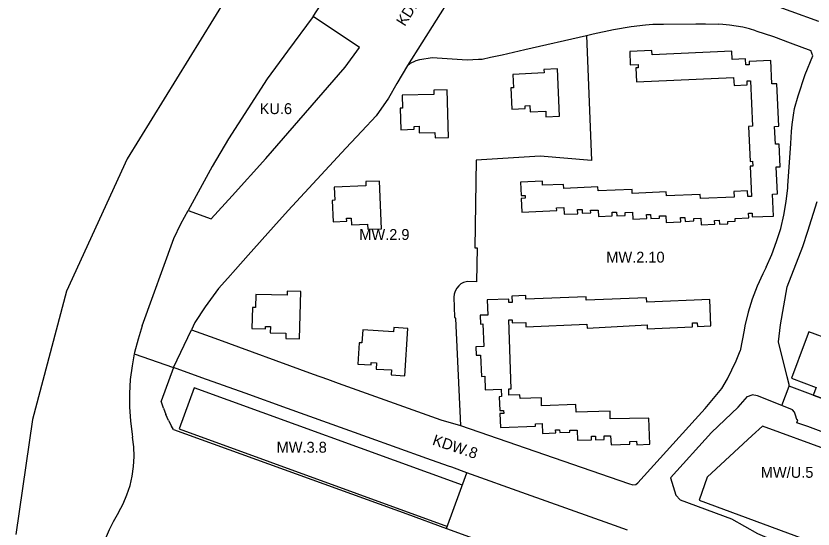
# Model space of a CAD drawing. Extents: x 7428239 to 7429836, y 5549133 to 5550853.
# Drawn here: x 7428328.4 to 7428694.2, y 5550030.9 to 5550266.4 of the extents above; entities that cross this region are included whole.
import ezdxf

# ---------------------------------------------------------------- set-up
doc = ezdxf.new("R2010")
doc.units = 0
for name, color, linetype in [('LIN_linie rozgraniczające', 7, 'Continuous'), ('LIN_nieprzekraczalna linia zabudowy', 7, 'Continuous'), ('LIN_obowiązująca linia zabudowy', 7, 'Continuous'), ('TXT_Oznaczenia Przeznaczenia', 7, 'Continuous')]:
    doc.layers.add(name, color=color, linetype=linetype)

msp = doc.modelspace()

# ---------------------------------------------------------------- linework, layer by layer
at = {"layer": 'LIN_linie rozgraniczające'}
for p, q in [((7428464.78, 5550266.18), (7428486.59, 5550299.96)), ((7428528.83, 5550276.64), (7428508.09, 5550243.65)), ((7428486.06, 5550251.96), (7428464.78, 5550266.18)), ((7428479.54, 5550242.96), (7428486.06, 5550251.96)), ((7428694.09, 5550248.12), (7428693.18, 5550250.53)), ((7428443.14, 5550200.99), (7428479.54, 5550242.96)), ((7428499.35, 5550228.63), (7428493.77, 5550220.64)), ((7428493.77, 5550220.64), (7428487.09, 5550213.47)), ((7428487.09, 5550213.47), (7428479.83, 5550205.67)), ((7428479.83, 5550205.67), (7428453.32, 5550177.17)), ((7428427.7, 5550183.88), (7428443.14, 5550200.99)), ((7428417.98, 5550173.31), (7428427.7, 5550183.88)), ((7428404.11, 5550171.01), (7428407.41, 5550177.08)), ((7428407.41, 5550177.08), (7428417.98, 5550173.31)), ((7428453.32, 5550177.17), (7428446.54, 5550169.55)), ((7428400.9, 5550164.25), (7428404.11, 5550171.01)), ((7428435.04, 5550156.63), (7428446.54, 5550169.55)), ((7428386.41, 5550124.13), (7428400.9, 5550164.25)), ((7428538.94, 5550159.95), (7428539.99, 5550159.97)), ((7428539.99, 5550159.97), (7428539.8, 5550144.41)), ((7428435.04, 5550156.63), (7428429.23, 5550150.1)), ((7428429.23, 5550150.1), (7428425.63, 5550146.08)), ((7428425.63, 5550146.08), (7428421.38, 5550141.34)), ((7428535.56, 5550144.51), (7428533.74, 5550144.09)), ((7428421.38, 5550141.34), (7428415.2, 5550132.9)), ((7428530.7, 5550141.4), (7428530, 5550140.05)), ((7428531.58, 5550142.56), (7428530.7, 5550141.4)), ((7428532.55, 5550143.4), (7428531.58, 5550142.56)), ((7428533.74, 5550144.09), (7428532.55, 5550143.4)), ((7428679.2, 5550124.67), (7428682.3, 5550142.05)), ((7428529.55, 5550138.74), (7428529.37, 5550137.28)), ((7428529.37, 5550137.28), (7428529.71, 5550128.19)), ((7428530, 5550140.05), (7428529.55, 5550138.74)), ((7428415.2, 5550132.9), (7428410.56, 5550125.65)), ((7428529.71, 5550128.19), (7428530.19, 5550127.56)), ((7428530.19, 5550127.56), (7428532.45, 5550078.39)), ((7428410.56, 5550125.65), (7428408.98, 5550122.32)), ((7428678.37, 5550116.76), (7428679.2, 5550124.67)), ((7428400.7, 5550104.99), (7428408.98, 5550122.32)), ((7428408.98, 5550122.32), (7428419.68, 5550118.44)), ((7428662.55, 5550122.24), (7428660.79, 5550112.72)), ((7428419.68, 5550118.44), (7428464.85, 5550102.05)), ((7428658.93, 5550108.11), (7428660.79, 5550112.72)), ((7428382.75, 5550111.37), (7428400.7, 5550104.99)), ((7428654.98, 5550099.8), (7428658.93, 5550108.11)), ((7428400.7, 5550104.99), (7428395.13, 5550089.64)), ((7428413.75, 5550100.32), (7428400.7, 5550104.99)), ((7428464.85, 5550102.05), (7428471.44, 5550099.69)), ((7428433.61, 5550093.21), (7428413.75, 5550100.32)), ((7428471.44, 5550099.69), (7428476.34, 5550097.92)), ((7428476.34, 5550097.92), (7428523.39, 5550081.02)), ((7428652.29, 5550095.38), (7428654.98, 5550099.8)), ((7428644.74, 5550086.16), (7428652.29, 5550095.38)), ((7428679.8, 5550087.58), (7428683.29, 5550096.41)), ((7428396.14, 5550086.34), (7428395.13, 5550089.64)), ((7428452.98, 5550086.26), (7428433.61, 5550093.21)), ((7428396.14, 5550086.34), (7428397.2, 5550083.53)), ((7428489.73, 5550073.1), (7428452.98, 5550086.26)), ((7428640.07, 5550081.15), (7428644.74, 5550086.16)), ((7428398.43, 5550080.79), (7428397.2, 5550083.53)), ((7428336.04, 5550081.17), (7428328.43, 5550028.45)), ((7428398.43, 5550080.79), (7428399.83, 5550078.14)), ((7428613.76, 5550052.06), (7428640.07, 5550081.15)), ((7428400.79, 5550076.64), (7428399.83, 5550078.14)), ((7428400.79, 5550076.64), (7428507.72, 5550037.84)), ((7428532.45, 5550078.39), (7428609.58, 5550051.75)), ((7428516.97, 5550063.33), (7428489.73, 5550073.1)), ((7428526.89, 5550059.77), (7428516.97, 5550063.33)), ((7428526.04, 5550031.19), (7428535.32, 5550056.75)), ((7428528.37, 5550059.24), (7428526.89, 5550059.77)), ((7428609.58, 5550051.75), (7428611.47, 5550051.24)), ((7428611.47, 5550051.24), (7428612.89, 5550051.37)), ((7428612.89, 5550051.37), (7428613.76, 5550052.06)), ((7428600.93, 5550033.25), (7428562.63, 5550046.97)), ((7428609.06, 5550030.33), (7428600.93, 5550033.25))]:
    msp.add_line(p, q, dxfattribs=at)
for points in [[(7428540.94, 5550471.5), (7428527.62, 5550433.97), (7428484.97, 5550367.83), (7428424.73, 5550274.49), (7428379.41, 5550200.89), (7428351.69, 5550140.08), (7428336.04, 5550081.17)], [(7428665.17, 5550274.78), (7428671.25, 5550273.2), (7428696.63, 5550264.05)], [(7428464.78, 5550266.18), (7428453.07, 5550250.24), (7428443.69, 5550237.53), (7428425.98, 5550210.05), (7428418.45, 5550197.38), (7428407.41, 5550177.08)], [(7428508.09, 5550243.65), (7428509.11, 5550244.58), (7428512.14, 5550245.99), (7428513.77, 5550246.5), (7428519.4, 5550247.35), (7428535.4, 5550246.28), (7428540.72, 5550246.51), (7428542.29, 5550246.65), (7428546.23, 5550247.48), (7428551.59, 5550248.62), (7428561.96, 5550251.01), (7428590.2, 5550257.4), (7428593.29, 5550258.17), (7428602.64, 5550260.17), (7428610.75, 5550261.58), (7428617.36, 5550262.36), (7428620.6, 5550262.6), (7428623.19, 5550262.6), (7428625.56, 5550262.69), (7428640.47, 5550262.72), (7428644.86, 5550262.74), (7428650.94, 5550262.57)], [(7428667.95, 5550259.6), (7428664.98, 5550260.49), (7428661.97, 5550261.22), (7428658.93, 5550261.8), (7428655.86, 5550262.23), (7428652.77, 5550262.49), (7428650.94, 5550262.57)], [(7428667.95, 5550259.6), (7428676.02, 5550256.95), (7428683.67, 5550254.15), (7428693.18, 5550250.53)], [(7428590.2, 5550257.4), (7428592.52, 5550200.13), (7428569.03, 5550202.12), (7428539.63, 5550200.24), (7428538.94, 5550159.95)], [(7428682.66, 5550188.41), (7428684, 5550207.84), (7428684.37, 5550213.36), (7428684.64, 5550216.59), (7428685.25, 5550220.87), (7428685.75, 5550223.97), (7428687.35, 5550229.69), (7428690.55, 5550239.58), (7428694.09, 5550248.12)], [(7428508.09, 5550243.65), (7428503.27, 5550235.43), (7428499.35, 5550228.63)], [(7428672.64, 5550151.17), (7428675.25, 5550156.93), (7428677.49, 5550162.84), (7428679.35, 5550168.89), (7428680.83, 5550175.04), (7428681.91, 5550181.27), (7428682.6, 5550187.55), (7428682.66, 5550188.41)], [(7428682.3, 5550142.05), (7428689.53, 5550160.66), (7428691.77, 5550167.64), (7428696.15, 5550181.23)], [(7428672.64, 5550151.17), (7428671.13, 5550148.1)], [(7428539.8, 5550144.41), (7428535.56, 5550144.51)], [(7428671.13, 5550148.1), (7428668.52, 5550142.34), (7428666.28, 5550136.43), (7428664.42, 5550130.38), (7428662.94, 5550124.23), (7428662.55, 5550122.24)], [(7428386.41, 5550124.13), (7428384.45, 5550118.11), (7428382.87, 5550111.99), (7428382.75, 5550111.37), (7428381.69, 5550105.78), (7428380.9, 5550099.5), (7428380.51, 5550093.19), (7428380.52, 5550086.87), (7428380.92, 5550080.56), (7428381.73, 5550074.28), (7428381.92, 5550073.12)], [(7428683.29, 5550096.41), (7428683.29, 5550097.21), (7428682.38, 5550100.84), (7428678.37, 5550116.76)], [(7428733.88, 5550078.05), (7428694.3, 5550092.41), (7428683.29, 5550096.41)], [(7428659.8, 5550086.81), (7428664.15, 5550091.74), (7428666.26, 5550092.52)], [(7428679.8, 5550087.58), (7428668.65, 5550091.99), (7428666.26, 5550092.52)], [(7428659.8, 5550086.81), (7428647.66, 5550075.24), (7428628.82, 5550054.34)], [(7428761.01, 5550059.22), (7428759.96, 5550058.64), (7428755.65, 5550058.66), (7428754.95, 5550058.66), (7428754.25, 5550058.97), (7428745.09, 5550062.01), (7428730.44, 5550066.4), (7428729.5, 5550066.01), (7428727.12, 5550065.03), (7428714.51, 5550069.34), (7428691.75, 5550077.92), (7428686.8, 5550079.72), (7428687.28, 5550081.07), (7428686.76, 5550081.22), (7428686.13, 5550083.11), (7428685.63, 5550084.53), (7428684.79, 5550085.6), (7428679.8, 5550087.58)], [(7428523.39, 5550081.02), (7428532.45, 5550078.39)], [(7428375.46, 5550038.45), (7428377.6, 5550042.41), (7428379.38, 5550046.54), (7428380.78, 5550050.82), (7428381.81, 5550055.2), (7428382.43, 5550059.66), (7428382.66, 5550064.15), (7428382.49, 5550068.65), (7428381.93, 5550073.11), (7428381.92, 5550073.12)], [(7428562.63, 5550046.97), (7428535.32, 5550056.75), (7428528.37, 5550059.24)], [(7428628.82, 5550054.34), (7428631.27, 5550046.51), (7428633.22, 5550044.37), (7428656.8, 5550035.59), (7428668.69, 5550028.81), (7428681.6, 5550023.4), (7428694.78, 5550018.71)], [(7428375.46, 5550038.45), (7428373.05, 5550034.2), (7428371.22, 5550030.6), (7428367.8, 5550022.68)], [(7428507.72, 5550037.84), (7428526.04, 5550031.19), (7428629.86, 5549993.52), (7428630.3, 5549993.32)]]:
    msp.add_lwpolyline(points, dxfattribs=at)
at = {"layer": 'LIN_nieprzekraczalna linia zabudowy'}
for points in [[(7428407.41, 5550177.08), (7428417.98, 5550173.31), (7428427.7, 5550183.88), (7428443.14, 5550200.99), (7428479.54, 5550242.96), (7428486.06, 5550251.96), (7428464.78, 5550266.18), (7428453.07, 5550250.24), (7428443.69, 5550237.53), (7428425.98, 5550210.05), (7428418.45, 5550197.38), (7428407.41, 5550177.08)], [(7428730.33, 5550102.14), (7428732.09, 5550106.68), (7428692.23, 5550121.39), (7428690.6, 5550117.05), (7428684.24, 5550100.1), (7428695.57, 5550095.81), (7428694.3, 5550092.41), (7428711.24, 5550086.26), (7428712.45, 5550089.61), (7428724.1, 5550085.39), (7428730.33, 5550102.14)], [(7428533.27, 5550051.11), (7428410.25, 5550095.78), (7428403.36, 5550076.85), (7428526.39, 5550032.14)], [(7428715.06, 5550061.91), (7428701.07, 5550067.07), (7428671.04, 5550078.17), (7428666.19, 5550073.87), (7428645.67, 5550054.64), (7428641.86, 5550044.19), (7428700.72, 5550022.48), (7428715.06, 5550061.91)]]:
    msp.add_lwpolyline(points, dxfattribs=at)
at = {"layer": 'LIN_obowiązująca linia zabudowy'}
for points in [[(7428570, 5550190.55), (7428559.98, 5550190.14), (7428560.23, 5550183.99), (7428562.06, 5550184.06), (7428562.11, 5550182.7), (7428560.32, 5550182.63), (7428560.58, 5550176.4), (7428576.6, 5550177.06), (7428576.53, 5550178.35), (7428579.87, 5550178.48), (7428580, 5550175.39), (7428586.2, 5550175.65), (7428586.13, 5550177.5), (7428588.23, 5550177.58), (7428588.3, 5550175.84), (7428592.18, 5550176), (7428592.13, 5550177.2), (7428595.57, 5550177.34), (7428595.69, 5550174.4), (7428602.07, 5550174.67), (7428602.01, 5550176.31), (7428604.04, 5550176.4), (7428604.1, 5550174.72), (7428607.96, 5550174.88), (7428607.9, 5550176.21), (7428611.29, 5550176.36), (7428611.43, 5550173.17), (7428617.89, 5550173.46), (7428617.81, 5550175.26), (7428619.6, 5550175.34), (7428619.69, 5550173.43), (7428623.76, 5550173.61), (7428623.71, 5550174.6), (7428626.7, 5550174.73), (7428626.84, 5550171.65), (7428633.51, 5550171.94), (7428633.42, 5550173.84), (7428635.42, 5550173.93), (7428635.5, 5550172.13), (7428639.46, 5550172.3), (7428639.41, 5550173.38), (7428642.68, 5550173.52), (7428642.81, 5550170.59), (7428649.05, 5550170.86), (7428648.98, 5550172.57), (7428651.15, 5550172.67), (7428651.23, 5550170.88), (7428655.12, 5550171.05), (7428655.07, 5550172.06), (7428658.45, 5550172.21), (7428658.39, 5550173.44), (7428664.66, 5550173.72), (7428664.56, 5550175.87), (7428666.2, 5550175.94), (7428666.28, 5550174.15), (7428675.99, 5550174.58), (7428675.55, 5550184.67), (7428677.86, 5550184.77), (7428677.32, 5550197.1), (7428679.16, 5550197.18), (7428678.7, 5550207.6), (7428676.92, 5550207.52), (7428676.56, 5550215.67), (7428678.41, 5550215.75), (7428677.54, 5550235.32), (7428675.22, 5550235.22), (7428674.75, 5550246.01), (7428664.86, 5550245.58), (7428664.93, 5550244), (7428663.35, 5550243.93), (7428663.23, 5550246.67), (7428657.04, 5550246.4), (7428656.87, 5550250.21), (7428620.32, 5550248.61), (7428620.27, 5550250.62), (7428610.04, 5550250.17), (7428610.31, 5550243.94), (7428613.94, 5550244.1), (7428614, 5550242.59), (7428612.84, 5550242.54), (7428613.12, 5550236.19), (7428657.75, 5550238.15), (7428657.92, 5550234.46), (7428663.98, 5550234.73), (7428663.89, 5550236.6), (7428665.41, 5550236.67), (7428666.33, 5550215.79), (7428664.58, 5550215.72), (7428665.28, 5550199.64), (7428666.46, 5550199.69), (7428666.56, 5550197.45), (7428665.36, 5550197.4), (7428665.96, 5550183.56), (7428664.28, 5550183.49), (7428664.16, 5550186.15), (7428657.86, 5550185.89), (7428657.98, 5550183.26), (7428642.51, 5550182.59), (7428642.43, 5550184.47), (7428626.92, 5550183.79), (7428626.84, 5550185.61), (7428611.22, 5550184.93), (7428611.14, 5550186.73), (7428595.56, 5550186.13), (7428595.49, 5550187.91), (7428579.79, 5550187.27), (7428579.72, 5550189.12), (7428570.08, 5550188.72)], [(7428556.47, 5550239.58), (7428556.77, 5550233.44), (7428555.5, 5550233.37), (7428555.97, 5550223.68), (7428562.06, 5550223.88), (7428562.02, 5550225.22), (7428564.27, 5550225.29), (7428564.37, 5550222.34), (7428571.5, 5550222.7), (7428571.61, 5550220.16), (7428577.77, 5550220.37), (7428576.86, 5550242.21), (7428570.71, 5550241.91), (7428570.79, 5550240.28)], [(7428505.62, 5550229.99), (7428505.78, 5550224.08), (7428504.74, 5550224.05), (7428505.01, 5550214.21), (7428511.2, 5550214.38), (7428511.16, 5550215.73), (7428513.41, 5550215.79), (7428513.5, 5550212.7), (7428520.65, 5550212.9), (7428520.72, 5550210.49), (7428526.86, 5550210.66), (7428526.26, 5550232.52), (7428520.14, 5550232.35), (7428520.2, 5550230.39)], [(7428474.52, 5550187.9), (7428474.77, 5550181.83), (7428473.58, 5550181.78), (7428473.99, 5550171.92), (7428480.2, 5550172.18), (7428480.14, 5550173.53), (7428482.31, 5550173.62), (7428482.43, 5550170.6), (7428489.75, 5550170.91), (7428489.85, 5550168.5), (7428496.1, 5550168.76), (7428495.18, 5550190.65), (7428488.93, 5550190.39), (7428489.01, 5550188.5)], [(7428438.5, 5550138.57), (7428438.34, 5550132.52), (7428436.95, 5550132.56), (7428436.7, 5550122.91), (7428442.95, 5550122.74), (7428442.98, 5550123.9), (7428445.21, 5550123.84), (7428445.13, 5550120.95), (7428452.31, 5550120.76), (7428452.24, 5550118.4), (7428458.52, 5550118.24), (7428459.08, 5550139.98), (7428452.86, 5550140.14), (7428452.81, 5550138.19)], [(7428646.76, 5550136.28), (7428617.95, 5550135), (7428617.83, 5550136.96), (7428590.14, 5550135.89), (7428590.07, 5550137.55), (7428562.39, 5550136.43), (7428562.32, 5550138.08), (7428556.03, 5550137.84), (7428556.14, 5550134.88), (7428554.59, 5550134.85), (7428554.54, 5550136.43), (7428544.7, 5550136.09), (7428544.96, 5550129.14), (7428541.44, 5550129), (7428541.59, 5550125.01), (7428542.65, 5550125.05), (7428543.05, 5550114.66), (7428539.42, 5550114.55), (7428539.59, 5550110.7), (7428541.63, 5550110.75), (7428542.09, 5550100.96), (7428543.57, 5550101.05), (7428543.8, 5550094.86), (7428551.1, 5550095.14), (7428551.23, 5550091.69), (7428550.16, 5550091.65), (7428550.41, 5550085.29), (7428552.19, 5550085.36), (7428552.24, 5550083.96), (7428550.47, 5550083.89), (7428550.71, 5550077.44), (7428566.8, 5550078.06), (7428566.76, 5550079.23), (7428569.9, 5550079.35), (7428570.08, 5550074.82), (7428576.1, 5550075.05), (7428576.05, 5550076.44), (7428577.87, 5550076.51), (7428577.92, 5550075.26), (7428582.57, 5550075.43), (7428582.54, 5550076.21), (7428585.98, 5550076.34), (7428586.16, 5550071.64), (7428592.51, 5550071.89), (7428592.45, 5550073.52), (7428594.36, 5550073.6), (7428594.42, 5550071.92), (7428598.33, 5550072.07), (7428598.27, 5550073.61), (7428601.32, 5550073.73), (7428601.48, 5550069.55), (7428610.14, 5550069.88), (7428610.1, 5550071.11), (7428613.21, 5550071.23), (7428613.27, 5550069.54), (7428619.3, 5550069.87), (7428618.78, 5550081.83), (7428601.14, 5550081.42), (7428601.02, 5550085.05), (7428585.47, 5550084.53), (7428585.35, 5550088.03), (7428569.64, 5550087.51), (7428569.52, 5550091.08), (7428559.77, 5550090.76), (7428559.71, 5550092.46), (7428554.66, 5550092.29), (7428554.56, 5550095.23), (7428555.68, 5550095.27), (7428554.62, 5550127), (7428556.06, 5550127), (7428556.11, 5550125.48), (7428562.39, 5550125.69), (7428562.45, 5550123.69), (7428590.45, 5550124.96), (7428590.53, 5550123.12), (7428618.03, 5550124.58), (7428618.14, 5550122.79), (7428638.91, 5550123.78), (7428638.87, 5550125.5), (7428641.04, 5550125.58), (7428641.15, 5550123.84), (7428647.33, 5550124.17)], [(7428487.53, 5550122.3), (7428487.17, 5550116.31), (7428485.93, 5550116.39), (7428485.34, 5550106.61), (7428491.38, 5550106.25), (7428491.45, 5550107.39), (7428493.84, 5550107.25), (7428493.67, 5550104.36), (7428500.78, 5550103.93), (7428500.64, 5550101.63), (7428506.92, 5550101.25), (7428508.23, 5550123.02), (7428501.85, 5550123.4), (7428501.73, 5550121.44)]]:
    msp.add_lwpolyline(points, close=True, dxfattribs=at)

# ---------------------------------------------------------------- texts
at = {"layer": 'TXT_Oznaczenia Przeznaczenia'}
for s, rotation, p in [('KDL.1', 57.4454, (7428506.8, 5550261.35)), ('KDW.8', 341.6134, (7428519.17, 5550069.71))]:
    msp.add_text(s, height=5, rotation=rotation, dxfattribs=at).set_placement(p)
for s, p in [('KU.6', (7428440.26, 5550221.36)), ('MW.2.9', (7428485.97, 5550163.59)), ('MW.2.10', (7428599.31, 5550153.19)), ('MW.3.8', (7428448.03, 5550065.94)), ('MW/U.5', (7428670.2, 5550054.41))]:
    msp.add_text(s, height=5, dxfattribs=at).set_placement(p)

doc.saveas('drawing.dxf')
